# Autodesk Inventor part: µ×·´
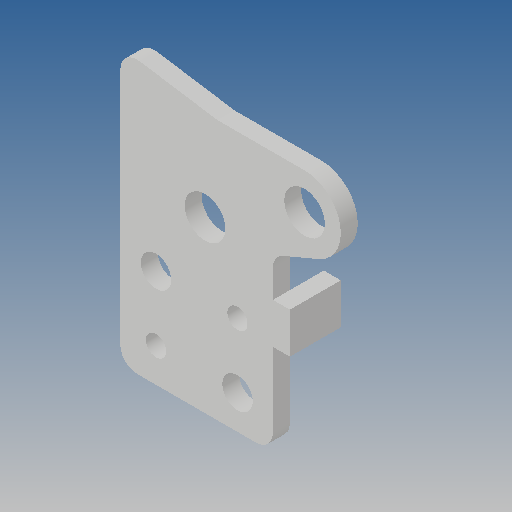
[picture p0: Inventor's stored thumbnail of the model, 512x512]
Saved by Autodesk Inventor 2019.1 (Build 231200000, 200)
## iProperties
Created: 2012-10
Part Number: µ×·´
Material: Ogólny
Document SubType Name: Modeling
Designer: CADENGINEERING4
Density: 1 g/cm^3
Appearance: Domyślna
Author: CADENGINEERING4
Revision Number: ÈÎºÎ
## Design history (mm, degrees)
feature "À­Éì2"
node "Bryła1"
